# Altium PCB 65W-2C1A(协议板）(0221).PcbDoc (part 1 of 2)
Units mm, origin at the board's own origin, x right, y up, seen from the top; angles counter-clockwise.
Board outline 49.16 x 94.2 mm, 4 copper layers (Top Layer, Mid-Layer 1, Mid-Layer 2, Bottom Layer); 54 components, 359 nets, 243 pads, 110 vias.
Unrouted connection lines stored in the file: 1.
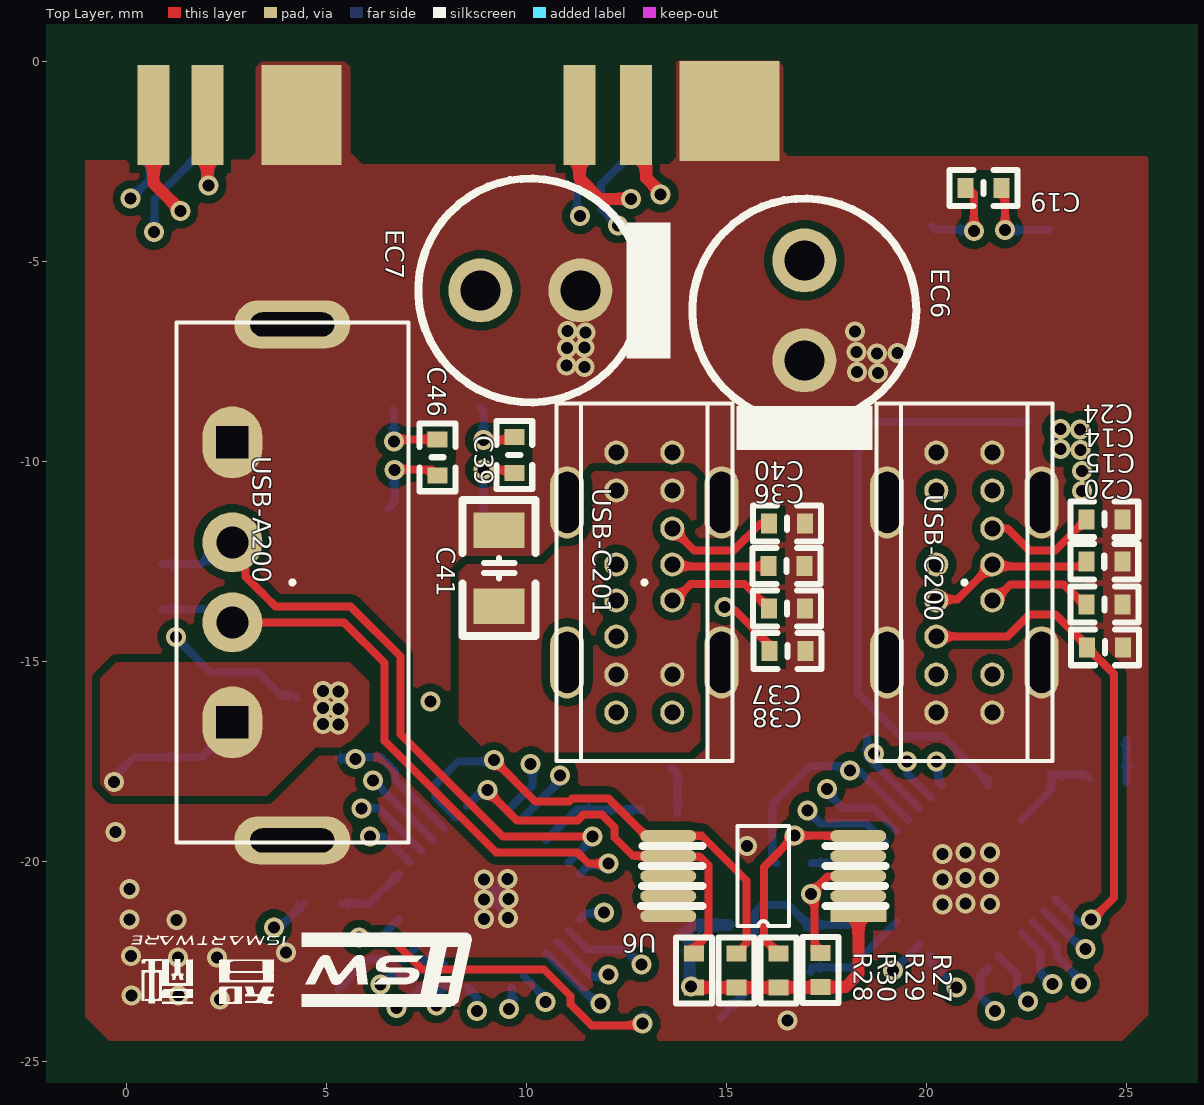
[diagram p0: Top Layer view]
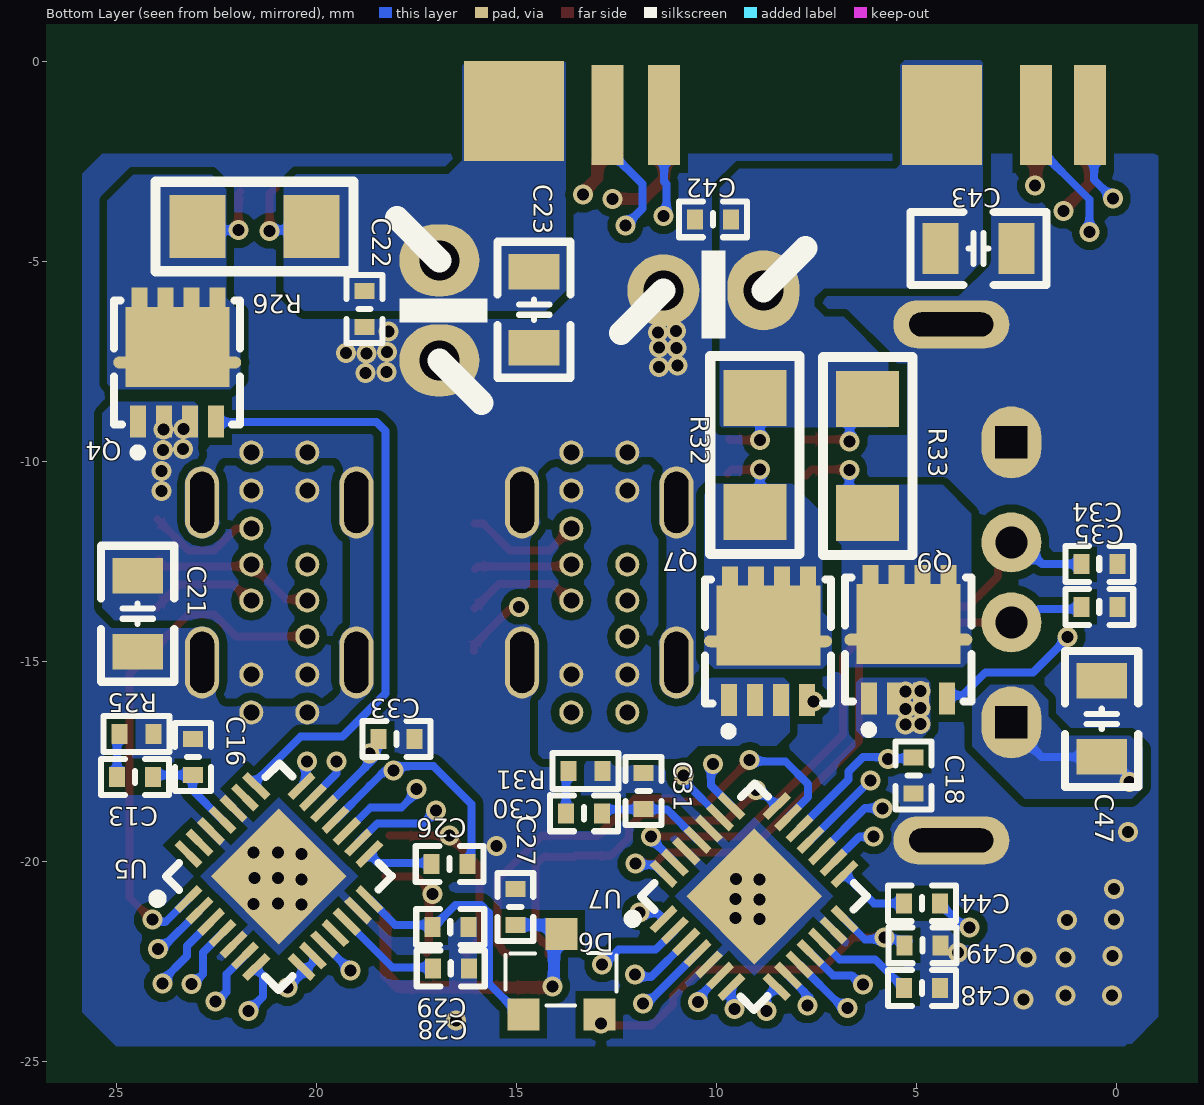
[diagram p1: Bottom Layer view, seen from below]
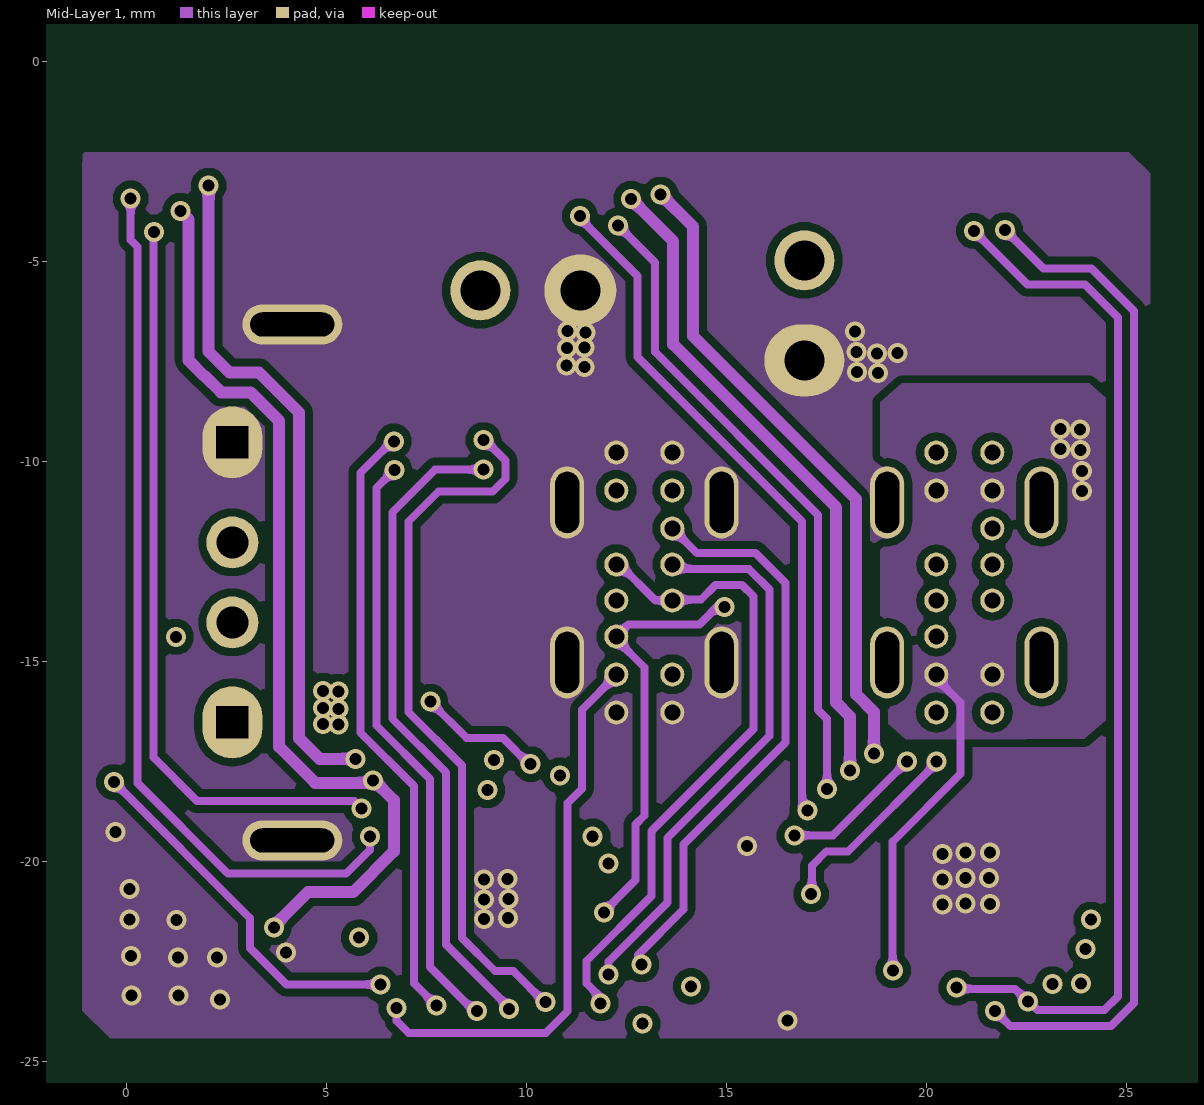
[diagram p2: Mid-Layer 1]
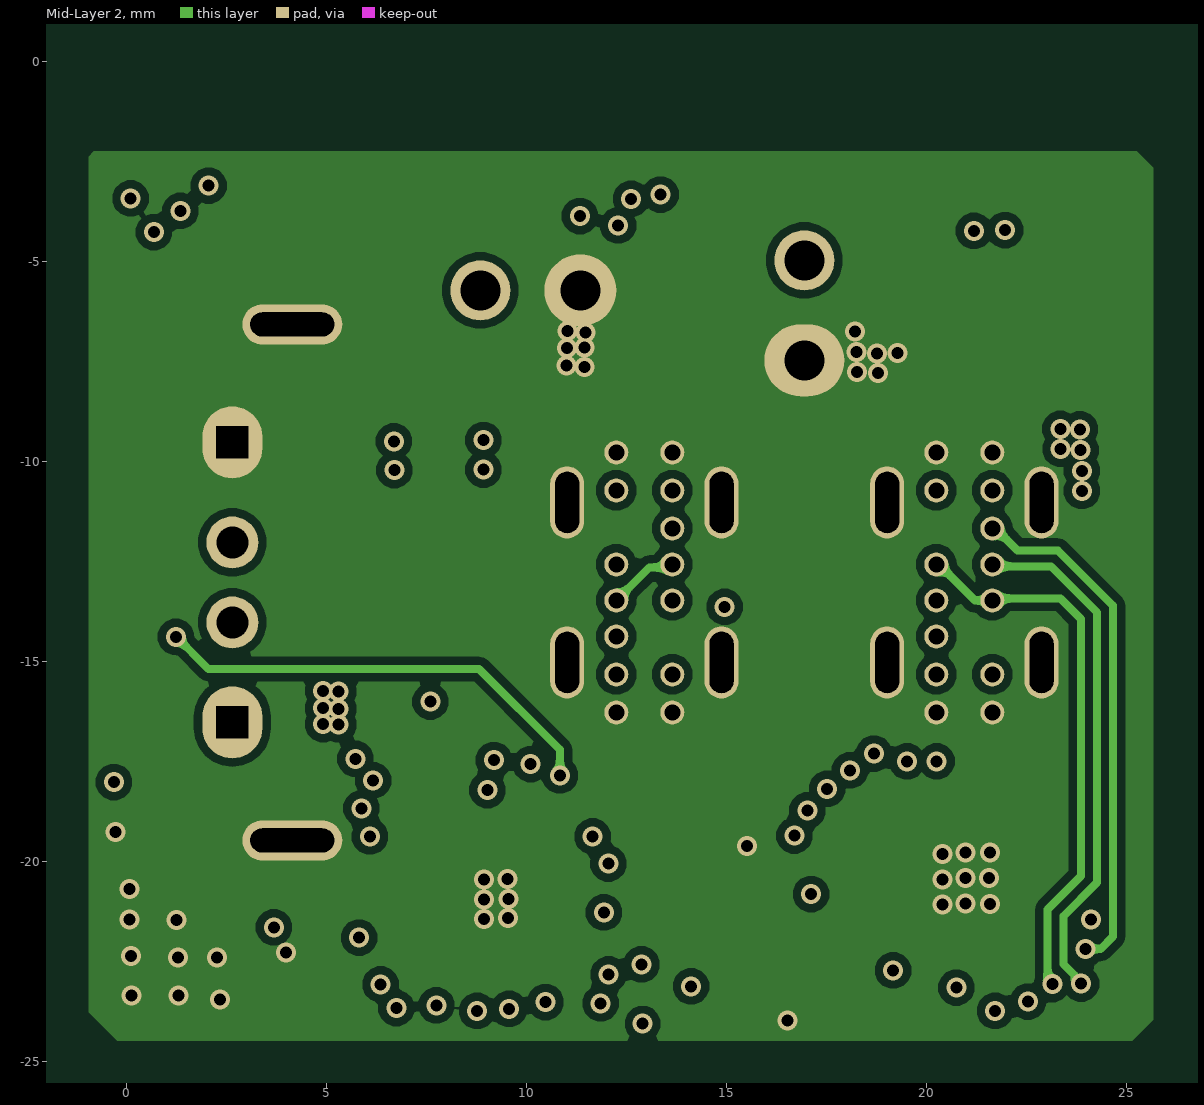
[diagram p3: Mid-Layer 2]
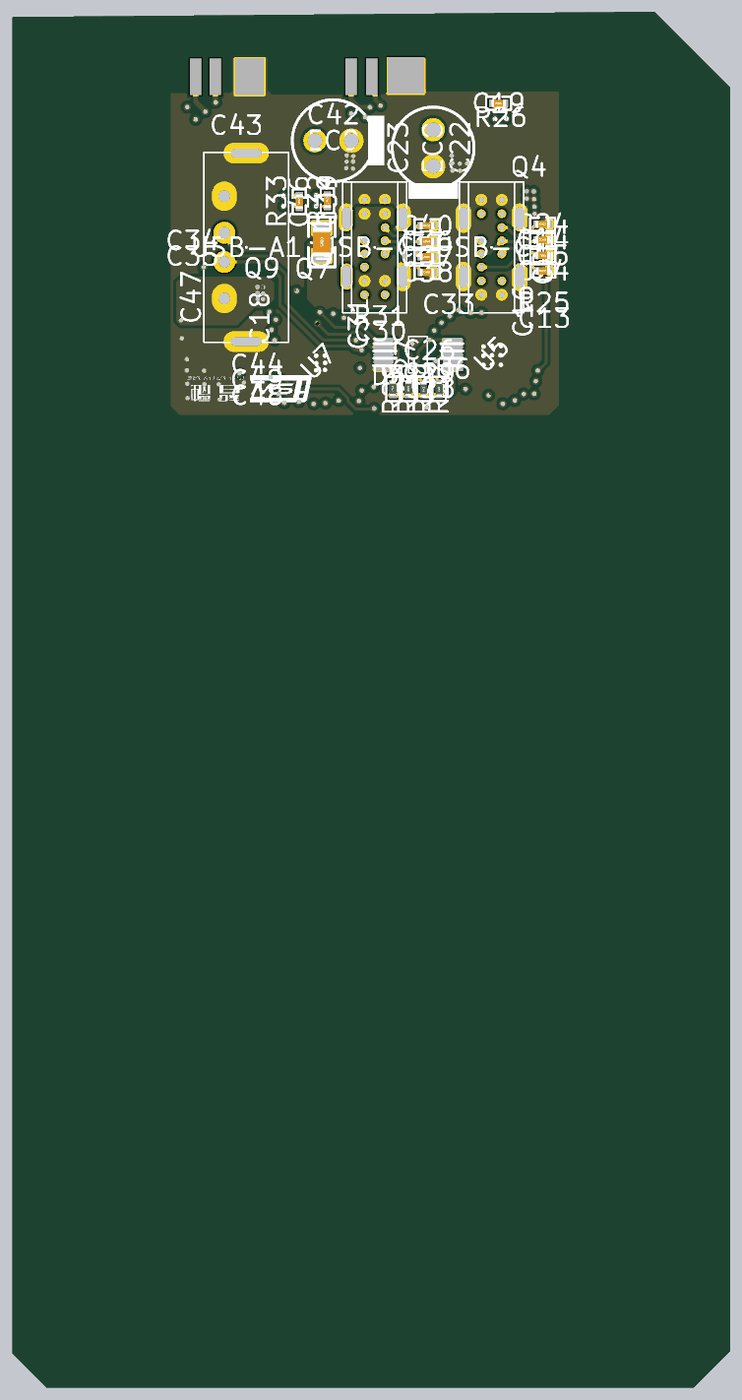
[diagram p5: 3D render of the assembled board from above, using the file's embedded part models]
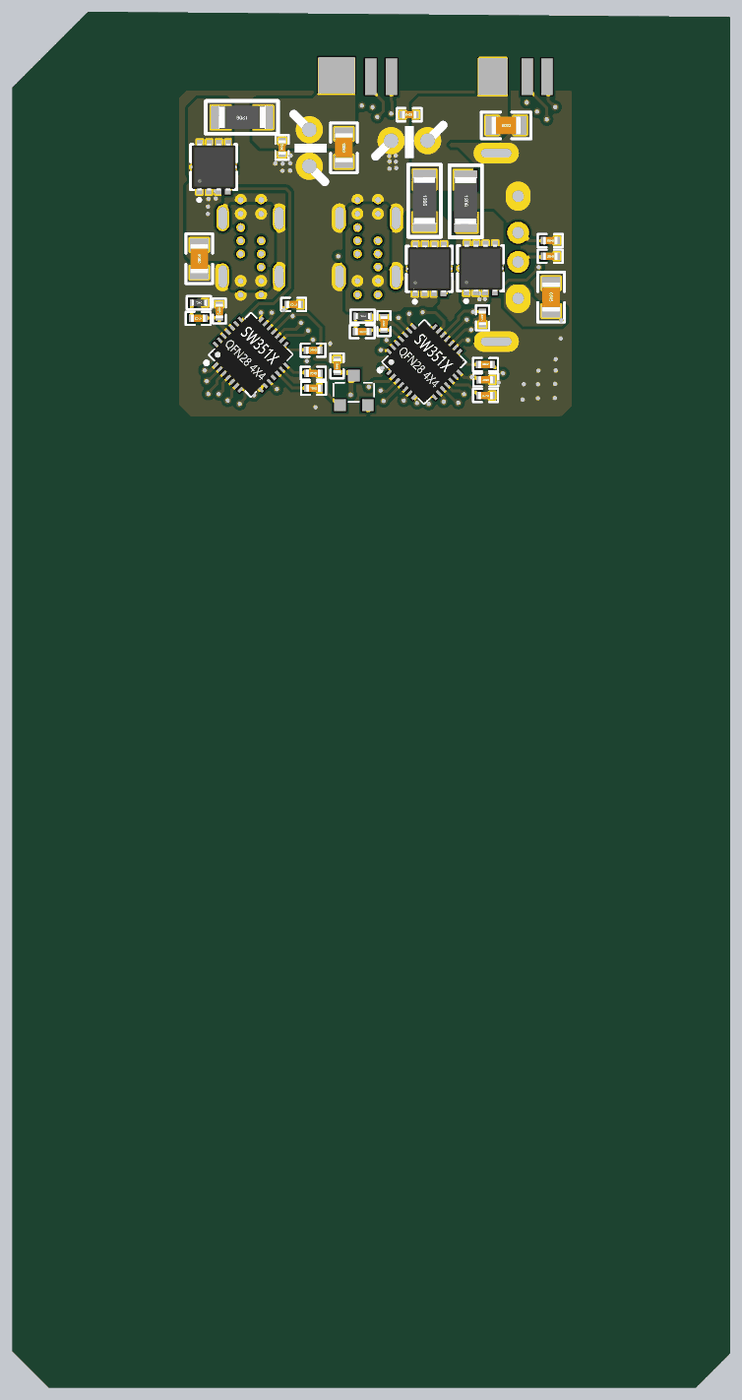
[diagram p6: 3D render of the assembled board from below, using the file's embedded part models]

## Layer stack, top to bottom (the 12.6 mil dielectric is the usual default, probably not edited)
Top Solder: solder mask 0.0102, Solder Resist, Dk 3.5
Top Layer: signal copper 0.0356
Dielectric1: core 0.32, FR-4, Dk 4.8
Mid-Layer 1: signal copper 0.0356
Dielectric2: prepreg 0.32, FR-4, Dk 4.8
Mid-Layer 2: signal copper 0.0356
Dielectric3: core 0.32, FR-4, Dk 4.8
Bottom Layer: signal copper 0.0356
Bottom Solder: solder mask 0.0102, Solder Resist, Dk 3.5

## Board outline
-11.88,2.75 -11.88,-88.76 -9.55,-91.09 34.78,-91.09 37.28,-88.59 37.28,-2.07 32.1,3.11

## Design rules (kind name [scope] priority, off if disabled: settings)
Clearance Clearance_2 [InNet('GND') And OnLayer('Mid-Layer 1') vs InNetClass('New Class')] p1: gap=0.8
Clearance Clearance_3 [InNet('GND') And OnLayer('Mid-Layer 2') vs InNetClass('New Class')] p2: gap=0.8
Clearance Clearance_1 [InNet('GND') And OnLayer('Top Layer') vs InNetClass('New Class')] p3: gap=1.2
Clearance [All] p4: gap=0.2
ComponentClearance [All] p1: gap=0 collisioncheckmode=3 verticalgap=0 showdistances=FALSE
HoleSize [All] p1 off: absolutevalues=TRUE maxlimit=2.54 minlimit=0.025 maxpercent=80.000 minpercent=20.000
MinimumSolderMaskSliver [All] p1 off: minsoldermaskwidth=0.254
NetAntennae [All] p1 off: netantennaetolerance=0
PlaneConnect [All] p1: planeconnectstyle=Direct reliefexpansion=0.508 reliefentries=4 reliefconductorwidth=0.254 reliefairgap=0.254
PolygonConnect [All] p1: connectstyle=Direct reliefconductorwidth=0.254 reliefentries=4 polygonreliefangle="90 Angle" airgapwidth=0.254
RoutingVias [All] p1: holewidth=0.3 width=0.5 viastyle="Through Hole" minholewidth=0.3 minwidth=0.5 maxholewidth=0.711 maxwidth=1.27
SilkToSilkClearance [All] p1 off: silktosilkclearance=0.254
SilkToSolderMaskClearance [IsPad] p1 off: minsilkscreentomaskgap=0.254 clearancetoexposedcopper=TRUE
SolderMaskExpansion [All] p1: expansion=0.102
Width [All] p1: maxlimit=3 minlimit=0.2 preferedwidth=0.2
23 further rules are at their usual default settings.

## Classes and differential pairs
net class "New Class": HHV HV NetC2_2 NetDB1_4
component class "P7-CEMK65W1A1CPD-P V0.2 20211227": CE1 CE2 RS2 RS3 RS4 RS5

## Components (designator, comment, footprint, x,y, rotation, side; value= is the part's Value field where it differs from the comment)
C13 "2.2nF/10V" "C 0402" 24.55,-17.88 r0 bottom
C14 "100pF/16V" "C 0402" 24.44,-12.5 r180 top
C15 "100pF/16V" "C 0402" 24.45,-13.57 r180 top
C16 "100pF/10V" "C 0402" 23.1,-17.38 r90 bottom
C18 "0.1uF/50V" "C 0402" 5.08,-17.85 r90 bottom
C19 "0.1uF/50V" "C 0402" 21.42,-3.16 r180 top
C20 "330pF/16V" "C 0402" 24.46,-14.64 r0 top (schematic designator C24)
C21 "10uF/25V" "C 0805" 24.48,-13.8 r90 bottom
C22 "0.1uF/50V" "C 0402" 18.81,-6.18 r90 bottom
C23 "22uF/25V" "C 0805" 14.57,-6.2 r90 bottom
C24 "330pF/16V" "C 0402" 24.44,-11.44 r0 top
C26 "0.1uF/50V" "C 0402" 16.68,-20.06 r180 bottom
C27 "Cap" "C 0402" 15.04,-21.13 r90 bottom
C28 "1uF/16V" "C 0402" 16.653,-22.667 r0 bottom
C29 "1uF/16V" "C 0402" 16.666,-21.636 r0 bottom
C30 "2.2nF/10V" "C 0402" 13.32,-18.79 r0 bottom
C31 "100pF/10V" "C 0402" 11.83,-18.23 r90 bottom
C33 "0.1uF/50V" "C 0402" 18.01,-16.93 r0 bottom
C34 "100pF/16V" "C 0402" 0.44,-12.56 r0 bottom
C35 "100pF/16V" "C 0402" 0.44,-13.63 r0 bottom
C36 "100pF/16V" "C 0402" 16.5,-12.61 r180 top
C37 "100pF/16V" "C 0402" 16.51,-13.67 r180 top
C38 "330pF/16V" "C 0402" 16.52,-14.73 r0 top
C39 "0.1uF/50V" "C 0402" 9.69,-9.83 r90 top
C40 "330pF/16V" "C 0402" 16.51,-11.55 r0 top
C41 "10uF/25V" "C 0805" 9.31,-12.66 r270 top
C42 "0.1uF/50V" "C 0402" 10.1,-3.94 r180 bottom
C43 "22uF/25V" "C 0805" 3.46,-4.67 r0 bottom
C44 "0.1uF/50V" "C 0402" 4.877,-21.04 r180 bottom
C46 "0.1uF/50V" "C 0402" 7.77,-9.89 r90 top
C47 "10uF/25V" "C 0805" 0.38,-16.43 r270 bottom
C48 "1uF/16V" "C 0402" 4.87,-23.16 r0 bottom
C49 "1uF/16V" "C 0402" 4.86,-22.09 r0 bottom
D6 "BAT54C/SOT-23" "SOD-23 - P" 13.89,-21.79 r180 bottom
EC6 "E - Cap" EC-5.5X9-P2.5-C#1 16.94,-6.218 r270 top locked (schematic designator EC8)
EC7 "E - Cap" EC-5.5X9-P2.5-C#2 10.09,-5.718 r0 top (schematic designator EC9)
Q4 "N MOS" PDFN-3*3 23.48,-7.52 r180 bottom
Q7 "N MOS" PDFN-3*3 8.71,-14.49 r180 bottom
Q9 "N MOS" PDFN-3*3 5.2,-14.45 r180 bottom
R25 "20K" "R 0402" 24.51,-16.81 r0 bottom
R26 "5mR" "R 1206" 21.56,-4.12 r0 bottom
R27 "2K" "R 0402" 17.35,-22.71 r90 top
R28 "2K" "R 0402" 14.18,-22.72 r270 top
R29 "2K" "R 0402" 16.29,-22.72 r90 top
R30 "2K" "R 0402" 15.24,-22.72 r270 top
R31 "20K" "R 0402" 13.29,-17.73 r0 bottom
R32 "5mR" "R 1206" 9.05,-9.83 r270 bottom
R33 "5mR" "R 1206" 6.23,-9.86 r270 bottom
U5 "SW3516P" SW351X_QFN28-4X4 20.95,-20.37 r225 bottom
U6 "MCU" MSOP10 18.29,-21.36 r180 top
U7 "SW3516P" SW351X_QFN28-4X4 9.07,-20.87 r225 bottom
USB-A200 "USB-A-5PIN" USB/AF/短体/10.0/直插/直边/蓝色/耐高温 4.14,-13.018 r0 top locked (schematic designator USB-A1)
USB-C200 "TYPE-C-14PIN" "TYPE-C 直立式外壳四脚14P" 20.94,-13.018 r0 top locked (schematic designator USB-C1)
USB-C201 "TYPE-C-14PIN" "TYPE-C 直立式外壳四脚14P" 12.94,-13.018 r0 top locked (schematic designator USB-C2)

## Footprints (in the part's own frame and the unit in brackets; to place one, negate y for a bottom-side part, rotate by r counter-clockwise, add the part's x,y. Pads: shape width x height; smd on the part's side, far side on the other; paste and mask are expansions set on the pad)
"C 0402" [mm] "无极性贴片电容"
  rect 0.4x0.5 smd: 1(-0.45,0) 2(0.45,0)
  silkscreen extent -0.85,-0.45 0.85,0.45, body extent -0.5,-0.26 0.5,0.26, height 0.53
"C 0805" [mm] "无极性贴片电容"
  rect 0.889x1.27 smd: 1(-0.95,0) 2(0.95,0)
  silkscreen extent -1.7,-0.91 1.7,0.91, body extent -1,-0.61 1,0.61, height 0.51
EC-5.5X9-P2.5-C#1 [mm]
  round 1.6 / inner round 1.5 / far side oval 1.8x2 hole 1 mask+0.03: 1(-1.25,0)
  round 1.6 / inner oval 1.8x2 / far side oval 1.8x2 hole 1 mask+0.03: 2(1.25,0)
  silkscreen extent -2.8,-2.8 3.49,2.8
EC-5.5X9-P2.5-C#2 [mm] "脚距2.5mm直径6.3mm高度7mm"
  round 1.6 / inner round 1.5 / far side oval 1.8x2 hole 1 mask+0.03: 1(-1.25,0)
  round 1.6 / inner round 1.8 / far side round 1.8 hole 1 mask+0.03: 2(1.25,0)
  silkscreen extent -2.8,-2.8 3.5,2.8
MSOP10 [mm]
  rect 1.4x0.3 smd mask+0.05: 1(0,0)
  oval 1.4x0.3 smd mask+0.05: 2(0,-0.5) 3(0,-1) 4(0,-1.5) 5(0,-2) 6(4.75,-2) 7(4.75,-1.5) 8(4.75,-1) 9(4.75,-0.5) 10(4.75,0)
  silkscreen extent -0.68,-2.25 5.43,0.25, body extent 0.7,-2.25 4.03,0.24, height 1.2
PDFN-3*3 [mm] "DFN3*3, PDFN3*3"
  rect 0.4x0.8 smd: 1(-0.992,-1.47) 2(-0.342,-1.47) 3(0.308,-1.47) 4(0.958,-1.47) 5(0.992,1.47) 6(0.341,1.47) 7(-0.309,1.47) 8(-0.959,1.47)
  oval 3.2x0.3 smd: 9(-0.012,0)
  rect 2.6x2 smd: 9(-0.005,0.393)
  silkscreen extent -1.59,-2.35 1.56,1.55, body extent -1.55,-1.6 1.55,1.6, height 0.8
"R 0402" [mm] "1/16W贴片电阻"
  rect 0.4x0.5 smd: 1(-0.425,0) 2(0.425,0)
  silkscreen extent -0.82,-0.45 0.83,0.45, body extent -0.52,-0.25 0.48,0.25, height 0.3
"R 1206" [mil] "1/4W贴片电阻"
  rect 55x62 smd: 1(-56.1,0) 2(56.1,0)
  silkscreen extent -97,-44 97,44, body extent -64,-31 62,31, height 22
"SOD-23 - P" [mm]
  rect 0.8x0.8 smd: 1(-0.95,-2.032) 2(0.95,-2.032) 3(0,-0.012)
  silkscreen extent -1.39,-1.81 1.38,-0.5
SW351X_QFN28-4X4 [mm] "28脚，长x宽x高：4x4x0.8mm，脚距：0.4mm"
  rect 0.2x0.8 smd: 1(-1.2,-2) 2(-0.8,-2) 3(-0.4,-2) 4(0,-2) 5(0.4,-2) 6(0.8,-2) 7(1.2,-2) 15(1.2,2) 16(0.8,2) 17(0.4,2) 18(0,2) 19(-0.4,2) 20(-0.8,2) 21(-1.2,2)
  rect 0.8x0.2 smd: 8(2,-1.2) 9(2,-0.8) 10(2,-0.4) 11(2,0) 12(2,0.4) 13(2,0.8) 14(2,1.2) 22(-2,1.2) 23(-2,0.8) 24(-2,0.4) 25(-2,0) 26(-2,-0.4) 27(-2,-0.8) 28(-2,-1.2)
  rect 2.4x2.4 smd: 29(0,0)
  silkscreen extent -2,-2.64 2,2.01, body extent -2.01,-2.01 2.01,2.01, height 0.75
"TYPE-C 直立式外壳四脚14P" [mm] "TYPE-C母座"
  round 0.6 hole 0.4: CC1(0.7,1.35) CC2(-0.7,-1.35) D+(-0.7,-0.45) D+(0.7,0.45) D-(-0.7,0.45) D-(0.7,-0.45) G(-0.7,-3.25) G(-0.7,3.25) G(0.7,-3.25) G(0.7,3.25) V(-0.7,-2.3) V(-0.7,2.3) V(0.7,-2.3) V(0.7,2.3)
  oval 0.85x1.8 hole 0.6 slot 1.53 at 90 deg: G(-1.93,-2) G(-1.93,2) G(1.93,-2) G(1.93,2)
  silkscreen extent -2.2,-4.47 2.2,4.47, body extent -2.2,-4.47 2.2,4.47, height 9.5
USB/AF/短体/10.0/直插/直边/蓝色/耐高温 [mm] "USB母座"
  oval 1.5x1.8 hole 0.8 square: 1(-1.5,3.5) 4(-1.5,-3.5)
  round 1.5 / inner round 1.3 / far side round 1.5 hole 0.8: 2(-1.5,1) 3(-1.5,-1)
  oval 2.9x1.2 / inner oval 2.5x1 / far side oval 2.9x1.2 hole 0.6 slot 2.1 at 0 deg: 5(0,-6.45) 6(0,6.45)
  silkscreen extent -2.9,-6.5 2.9,6.5, body extent -3.7,-6.5 3.7,6.5, height 6.7

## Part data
C13 C16 C18 C19 C20 C22 C23 C24 C26 C28 C29 C30 C31 C33 C38 C39 C40 C42 C43 C44 C46 C48 C49: library part CAP0603, "Capacitor"
C14 C15 C21 C34 C35 C36 C37 C41 C47: library part CAP0805, "Capacitor"
C27: "Capacitor"
D6: library part D3
EC6 EC7: "Electroytic Capacitor, 100uF/35V, ±20%, 105℃，Φ 6.5 * 12.0 mm"
Q4 Q7 Q9: library part AO3416_C479060
R25 R26 R27 R28 R29 R30 R31 R32 R33: library part RES, "Resistor"
U5 U7: library part SW3517, "IC"
U6: library part 153_MSOP10
USB-C200 USB-C201: "TYPE-C"

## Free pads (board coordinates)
  rect 0.8x2.5 smd far side: 0(0.67,-1.333) 0(2.02,-1.333) 0(11.32,-1.333) 0(12.738,-1.333)
  rect 0.8x2.5 smd: 0(0.67,-1.333) 0(2.02,-1.333) 0(11.32,-1.333) 0(12.738,-1.333)
  rect 2x2.5 smd far side: 0(4.37,-1.33)
  rect 2x2.5 smd: 0(4.37,-1.33)
  rect 2.5x2.5 smd far side: 0(15.07,-1.23)
  rect 2.5x2.5 smd: 0(15.07,-1.23)

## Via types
v1: diameter 0.5, hole 0.3, Top Layer to Bottom Layer, tented both sides, 110 vias

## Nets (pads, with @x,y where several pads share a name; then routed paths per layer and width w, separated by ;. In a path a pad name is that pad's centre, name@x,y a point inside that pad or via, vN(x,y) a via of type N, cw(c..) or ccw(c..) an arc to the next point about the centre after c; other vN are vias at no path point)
111: 
112: 
113: 
115: 
116: 
$$$3: 
$$$11: 
$$$13: 
$$$16: 
$$$18: 
$$$20: 
$$$24: 
$$$27: 
$$$28: 
$$$29: 
$$$31: 
$$$32: 
$$$37: 
$$$39: 
$$$40: 
$$$43: 
$$$51: 
AUX: 
BST2: 
BST_A: C26.1 U5.15 | length 1.7
  Bottom Layer w0.2: C26.1@17.12,-20.03 18.462,-20.03 U5.15@18.687,-19.804 ; U5.15@18.69,-19.83 U5.15@18.7,-19.82
BST_C: C44.1 U7.15 | length 1.7
  Bottom Layer w0.2: C44.1@5.37,-21.04 6.072,-21.04 U7.15@6.807,-20.304
CATHODE: 
CC1: 
CC1_A: C24.1 U5.2 USB-C200.CC1 | length 17.3
  Top Layer w0.2: USB-C200.CC1@21.56,-11.67 22.022,-11.67 22.57,-12.218 23.212,-12.218 C24.1@23.99,-11.44
  Mid-Layer 2 w0.2: USB-C200.CC1@21.65,-11.6 22.268,-12.218 23.278,-12.218 24.66,-13.6 24.66,-21.87 24.35,-22.18 v1(23.97,-22.18)
  Bottom Layer w0.2: U5.2@22.93,-21.219 23.881,-22.17 v1@23.94,-22.17
CC1_C: C40.1 U7.2 USB-C201.CC1 | length 19.5
  Top Layer w0.2: USB-C201.CC1@13.64,-11.668 14.19,-12.218 15.171,-12.218 15.839,-11.55 C40.1@16.06,-11.55
  Mid-Layer 1 w0.2: v1@12.85,-22.54 12.78,-22.47 12.78,-22.329 13.92,-21.189 13.92,-19.567 16.47,-17.017 16.47,-13.033 15.717,-12.28 14.252,-12.28 USB-C201.CC1@13.64,-11.668
  Bottom Layer w0.2: U7.2@11.05,-21.719 11.531,-22.2 12.46,-22.2 v1@12.84,-22.58
  other v1: 12.87,-22.57
CC2: 
CC2_A: C20.1 U5.1 USB-C200.CC2 | length 12.8
  Top Layer w0.2: USB-C200.CC2@20.24,-14.368 22.02,-14.368 22.57,-13.818 23.218,-13.818 C20.1@24.03,-14.63 ; C20.1@23.97,-14.66 C20.1@23.97,-14.62 ; C20.1@24.01,-14.64 24.68,-15.31 24.68,-20.9 v1@24.11,-21.47
  Bottom Layer w0.2: U5.1@23.213,-20.936 23.777,-21.5 v1@24.07,-21.5
  other v1: 24.11,-21.45
CC2_C: C38.1 U7.1 USB-C201.CC2 | length 12.8
  Top Layer w0.2: 15.2,-13.71 16.07,-14.58 C38.1@16.07,-14.73
  Mid-Layer 1 w0.2: v1@11.92,-21.26 12.72,-20.46 12.72,-19.07 12.94,-18.85 12.94,-15.14 12.242,-14.442 USB-C201.CC2@12.24,-14.368 ; USB-C201.CC2@12.21,-14.4 USB-C201.CC2@12.24,-14.368 ; v1(14.95,-13.63) v1@14.89,-13.63 ; v1@14.99,-13.53 v1@14.89,-13.63 ; USB-C201.CC2@12.24,-14.368 12.542,-14.068 14.32,-14.068 14.758,-13.63 v1@14.89,-13.63
  Bottom Layer w0.2: U7.1@11.333,-21.436 11.478,-21.29 v1@11.91,-21.29
  other v1: 11.93,-21.27
CC3: 
CC4: 
COMP: 
COMP2: 
COMP_A: C13.1 C16.1 U5.25 | length 2.5
  Bottom Layer w0.2: U5.25@22.364,-18.956 23.11,-18.21 C16.1@23.11,-17.83 ; C16.1@23.11,-17.78 C16.1@23.11,-17.83 ; C13.1@24.06,-17.92 23.97,-17.83 C16.1@23.11,-17.83
COMP_C: C30.1 C31.1 U7.25 | length 2.7
  Bottom Layer w0.2: U7.25@10.484,-19.456 11.25,-18.69 12.83,-18.69 C30.1@12.86,-18.72
CSN: 
CSNA: C46.1 Q9.5 Q9.6 Q9.7 Q9.8 Q9.9 R33.2 U7.8 | length 17.7
  Top Layer w0.2: v1@6.72,-10.18 6.73,-10.19 7.62,-10.19 C46.1@7.77,-10.34
  Mid-Layer 1 w0.2: v1(6.69,-10.21) 6.24,-10.66 6.24,-16.59 7.58,-17.93 7.58,-22.63 v1@8.71,-23.76
  Bottom Layer w0.2: R33.2@6.53,-11.17 6.69,-11.01 v1(6.69,-10.21) ; U7.8@8.504,-23.133 8.75,-23.378 v1@8.75,-23.8
  other v1: 8.76,-23.73
CSNC_A: C19.1 Q4.5 Q4.6 Q4.7 Q4.8 Q4.9 R26.2 U5.7 | length 28.6
  Top Layer w0.2: C19.1@21.91,-3.24 21.96,-3.29 v1(21.96,-4.21)
  Mid-Layer 1 w0.2: v1(21.71,-23.73) 22.09,-24.11 24.606,-24.11 25.18,-23.536 25.18,-6.23 24.12,-5.17 22.92,-5.17 v1(21.96,-4.21)
  Bottom Layer w0.2: U5.7@21.541,-22.659 21.35,-22.85 21.35,-23.37 v1(21.71,-23.73) ; v1(21.96,-4.21) 23.04,-4.21 R26.2@23.06,-4.19
CSNC_C: C39.1 Q7.5 Q7.6 Q7.7 Q7.8 Q7.9 R32.2 U7.7 | length 19.1
  Top Layer w0.2: v1(8.92,-10.2) 9.64,-10.2 C39.1@9.74,-10.3
  Mid-Layer 1 w0.2: v1(8.92,-10.2) 7.71,-10.2 6.64,-11.27 6.64,-16.424 7.98,-17.764 7.98,-22.07 v1@9.58,-23.67
  Bottom Layer w0.2: R32.2@8.87,-11.44 8.92,-11.39 v1(8.92,-10.2) ; v1@9.58,-23.74 9.636,-23.684 U7.7@9.636,-23.133
  other v1: 9.56,-23.68
CSPA: C39.2 C42.2 C43.2 C46.2 EC7.1 pad.0@4.37,-1.33 R32.1 R33.1 U7.6 U7.9 | length 38.6
  Top Layer w0.2: v1@6.68,-9.47 6.71,-9.44 C46.2@7.77,-9.44 ; v1(8.92,-9.46) 9.67,-9.46 C39.2@9.7,-9.43
  Mid-Layer 1 w0.2: v1(6.68,-9.49) 6.632,-9.49 5.84,-10.282 5.84,-16.77 7.18,-18.11 7.18,-23.04 v1@7.68,-23.54 ; v1@7.64,-23.58 v1@7.73,-23.67 ; v1@8.888,-9.39 v1@8.888,-9.382 ; v1@8.939,-9.441 9.47,-9.972 9.47,-10.428 9.148,-10.75 8.692,-10.75 7.79,-10.75 7.04,-11.5 7.04,-16.259 8.38,-17.599 8.38,-21.904 9.213,-22.737 9.667,-22.737 v1@10.46,-23.53
  Bottom Layer w0.2: R33.1@6.64,-8.71 6.68,-8.75 v1(6.68,-9.49) ; v1@7.69,-23.69 7.69,-23.381 U7.9@8.221,-22.85 ; R32.1@8.83,-8.64 8.92,-8.73 v1(8.92,-9.46) ; U7.6@9.919,-22.85 10.44,-23.371 v1@10.44,-23.55
  other v1: 7.74,-23.59 10.47,-23.51
CSPC: 
D+: 
DB+: 
DM: 
DMA: C35.2 U7.28 USB-A200.3 | length 16
  Top Layer w0.2: USB-A200.3@2.203,-14.267 USB-A200.3@2.546,-13.924 ; USB-A200.3@2.64,-14.018 5.433,-14.018 6.45,-15.036 6.45,-16.984 9.237,-19.77 11.272,-19.77 11.552,-20.05 v1(12.04,-20.05)
  Bottom Layer w0.2: C35.2@0.9,-13.68 1.95,-13.68 2.289,-14.018 USB-A200.3@2.64,-14.018 ; U7.28@11.333,-20.304 11.557,-20.08 v1@11.87,-20.08
DMA2: 
DMA2-R: 
DMC: 
DMC_A: C15.2 U5.4 USB-C200.D- | length 18.1
  Top Layer w0.2: USB-C200.D-@21.64,-13.468 21.692,-13.468 22.09,-13.07 23.43,-13.07 C15.2@24,-13.64
  Mid-Layer 2 w0.2: USB-C200.D-@20.26,-12.52 21.208,-13.468 USB-C200.D-@21.64,-13.468 ; USB-C200.D-@21.65,-13.36 21.71,-13.42 23.349,-13.42 23.86,-13.931 23.86,-20.357 23.02,-21.197 23.02,-22.96 v1@23.13,-23.07
  Bottom Layer w0.2: U5.4@22.364,-21.784 22.85,-22.27 22.85,-22.81 23.1,-23.06 v1(23.14,-23.06)
DMC_C: C37.2 U7.4 USB-C201.D- | length 20.8
  Top Layer w0.2: USB-C201.D-@13.68,-13.48 14.1,-13.06 15.45,-13.06 C37.2@16.06,-13.67
  Mid-Layer 1 w0.2: v1(11.85,-23.54) 11.85,-23.398 11.5,-23.048 11.5,-22.478 13.12,-20.858 13.12,-19.236 15.67,-16.686 15.67,-13.364 15.386,-13.08 14.722,-13.08 14.352,-13.45 USB-C201.D-@13.68,-13.45 ; USB-C201.D-@12.29,-12.54 13.218,-13.468 USB-C201.D-@13.64,-13.468
  Bottom Layer w0.2: U7.4@10.484,-22.284 11.76,-23.56 v1@11.87,-23.56 ; v1@11.85,-23.57 v1@11.88,-23.57
DP: 
DPA: C34.2 U7.27 USB-A200.2 | length 16.2
  Top Layer w0.2: USB-A200.2@2.64,-12.018 2.64,-12.37 2.972,-12.701 2.972,-12.872 3.307,-13.207 cw(c2.64,-14.018) 3.452,-13.352 3.718,-13.618 5.598,-13.618 6.85,-14.87 6.85,-16.818 9.402,-19.37 v1(11.65,-19.37)
  Bottom Layer w0.2: C34.2@0.89,-12.56 1.873,-12.56 2.363,-12.07 USB-A200.2@2.63,-12.07 ; U7.27@11.05,-20.021 v1@11.6,-19.471
DPA2-R: 
DPC: 
DPC_A: C14.2 U5.3 USB-C200.D+ | length 19.2
  Top Layer w0.2: USB-C200.D+@20.17,-13.44 20.769,-13.44 USB-C200.D+@21.64,-12.568 21.69,-12.618 23.792,-12.618 C14.2@23.96,-12.45
  Mid-Layer 2 w0.2: USB-C200.D+@21.64,-12.568 21.69,-12.618 23.113,-12.618 24.26,-13.766 24.26,-20.522 23.42,-21.362 23.42,-22.562 23.69,-22.832 23.69,-22.95 v1@23.82,-23.08
  Bottom Layer w0.2: U5.3@22.647,-21.501 23.25,-22.104 23.25,-22.36 v1@23.89,-23
  other v1: 23.86,-23.05
DPC_C: C36.2 U7.3 USB-C201.D+ | length 19.9
  Top Layer w0.2: USB-C201.D+@13.64,-12.568 13.69,-12.618 15.988,-12.618 C36.2@16.05,-12.68
  Mid-Layer 1 w0.2: v1@12.01,-22.87 v1@12.01,-22.82 ; v1(12.05,-22.82) 12.05,-22.493 13.52,-21.024 13.52,-19.401 16.07,-16.851 16.07,-13.199 15.551,-12.68 13.752,-12.68 USB-C201.D+@13.64,-12.568
  Mid-Layer 2 w0.2: USB-C201.D+@12.24,-13.468 13.064,-12.645 13.535,-12.645 USB-C201.D+@13.62,-12.56
  Bottom Layer w0.2: U7.3@10.767,-22.001 11.646,-22.88 v1@12.03,-22.88
EN: 
FB-G: 
FB_C: 
FB_IC: 
GATEA: Q9.4 U7.23 | length 16.6
  Mid-Layer 2 w0.2: v1@1.2,-14.34 2.04,-15.18 8.81,-15.18 10.83,-17.2 v1(10.83,-17.845)
  Bottom Layer w0.2: v1@1.21,-14.38 2.1,-15.27 3.29,-15.27 3.859,-15.839 4.161,-15.839 Q9.4@4.242,-15.92 ; U7.23@9.919,-18.89 10.773,-18.036 10.773,-17.877 v1@10.85,-17.8
  other v1: 1.23,-14.38
GATEC_A: Q4.4 U5.22 | length 15.1
  Bottom Layer w0.2: 18.66,-16.17 18.285,-15.795 18.285,-9.235 18.51,-9.01 Q4.4@22.48,-9.01 ; 18.661,-16.169 18.71,-16.218 18.71,-16.22 19.358,-16.868 20.406,-16.868 21.526,-17.989 U5.22@21.526,-18.096 ; Q4.4@22.5,-9.012 Q4.4@22.522,-8.99
GATEC_C: Q7.4 U7.22 | length 4.6
  Top Layer w0.2: v1@10.058,-17.56 v1(10.1,-17.56)
  Mid-Layer 1 w0.2: v1(7.59,-16) 8.5,-16.91 9.408,-16.91 10.098,-17.6 v1@10.19,-17.6
  Bottom Layer w0.2: U7.22@9.636,-18.607 10.15,-18.093 v1@10.15,-17.48
GND: 
GND2: 
GND_FIELD_SIGNAL: 
GNDA: 
GNDC1: 
GNDC2: 
HD: 
HGATE2: 
HGATE_A: pad.0@12.738,-1.333 U5.17 | length 21.7
  Mid-Layer 1 w0.2: v1(12.286,-4.095) 13.21,-5.019 13.21,-7.254 17.285,-11.329 17.285,-16.208 17.51,-16.432 v1(17.51,-18.18)
  Bottom Layer w0.2: v1(12.286,-4.095) 11.862,-3.671 11.862,-3.06 12.738,-2.183 pad.0@12.738,-1.333 ; v1@17.48,-18.24 17.88,-18.64 18.654,-18.64 U5.17@19.253,-19.239
HGATE_C: pad.0@2.02,-1.333 U7.17 | length 24.5
  Mid-Layer 1 w0.2: v1(0.68,-4.26) 0.67,-4.27 0.67,-17.39 1.76,-18.48 5.69,-18.48 5.865,-18.655 v1(5.865,-18.665)
  Bottom Layer w0.2: v1@0.69,-4.15 0.69,-3.44 2.02,-2.11 pad.0@2.02,-1.333 ; pad.0@1.72,-1.41 pad.0@1.92,-1.21 ; v1(5.865,-18.665) 5.87,-18.66 6.294,-18.66 U7.17@7.373,-19.739
HHV: 
HV: 
HVDC: 
INCAT: 
IS: 
L: 
LG: 
LGATE2: 
LGATE_A: pad.0@11.32,-1.333 U5.16 | length 22
  Mid-Layer 1 w0.2: v1(11.331,-3.859) 11.331,-3.917 12.77,-5.357 12.77,-7.379 16.885,-11.495 16.885,-18.585 v1(17.02,-18.72)
  Bottom Layer w0.2: pad.0@11.32,-1.333 11.32,-2.994 11.254,-3.06 11.254,-3.701 11.35,-3.797 v1@11.35,-3.81 ; v1@17.06,-18.77 17.33,-19.04 18.489,-19.04 U5.16@18.97,-19.521
LGATE_C: pad.0@0.67,-1.333 U7.16 | length 25.5
  Mid-Layer 1 w0.2: v1@0.1,-3.4 0.1,-4.458 0.27,-4.628 0.27,-18.034 2.536,-20.3 5.484,-20.3 6.08,-19.704 v1(6.08,-19.37)
  Bottom Layer w0.2: v1(0.1,-3.42) 0.57,-2.95 0.57,-1.433 pad.0@0.67,-1.333 ; v1@6.18,-19.38 6.449,-19.38 U7.16@7.09,-20.021
LSG: 
LSGA: 
LSGC: 
MOD: 
N: 
N16857873: 
N16857912: 
N16858127: 
N16870552: 
N16870687: 
N16870705: 
N16870765: 
N16874562: 
N16975475: 
NetBD1_1: 
NetC1_2: 
NetC2_1: 
NetC2_2: 
NetC3_2: 
NetC4_1: 
NetC4_2: 
NetC5_1: 
NetC5_2: 
NetC6_1: 
NetC6_2: 
NetC7_1: 
NetC7_2: 
NetC8_1: 
NetC10_1: 
NetC11_1: 
NetC11_2: 
NetC12_1: 
NetC13_2: C13.2 R25.2 | length 1.1
  Bottom Layer w0.2: C13.2@25,-18.02 R25.2@25,-16.95
NetC14_1: 
NetC14_2: 
NetC15_1: 
NetC15_2: 
NetC16_1: 
NetC17_1: 
NetC19_1: 
NetC20_1: 
NetC21_1: 
NetC22_1: 
NetC22_2: 
NetC23_1: 
NetC23_2: 
NetC24_2: 
NetC25_1: 
NetC25_2: 
NetC27_2: 
NetC28_1: 
NetC28_2: 
NetC29_1: 
NetC29_2: 
NetC30_1: 
NetC30_2: C30.2 R31.2 | length 1.2
  Bottom Layer w0.2: R31.2@13.62,-17.66 13.77,-17.81 C30.2@13.77,-18.79
NetC32_1: 
NetC33_1: 
NetC35_1: 
NetC35_2: 
NetC37_1: 
NetC200_2: 
NetC201_2: 
NetC202_2: 
NetC203_2: 
NetC204_2: 
NetC205_2: 
NetC206_1: 
NetC207_1: 
NetC208_1: 
NetC208_2: 
NetC209_1: 
NetC209_2: 
NetC210_2: 
NetC211_2: 
NetC219_1: 
NetC220_1: 
NetC221_2: 
NetC222_1: 
NetC224_2: 
NetC226_2: 
NetC227_1: 
NetC228_1: 
NetCE2_1: 
NetCX1_1: 
NetCX1_2: 
NetCY2_1: 
NetD1_2: 
NetD2_1: 
NetD2_2: 
NetD3_1: 
NetD3_2: 
NetD4_1: 
NetD4_2: 
NetD5_1: 
NetD5_2: 
NetD6_1: 
NetD6_2: 
NetD200_1: 
NetD201_1: 
NetD202_1: 
NetD203_1: 
NetD205_1: 
NetD205_2: 
NetD206_1: 
NetD207_1: 
NetD208_1: 
NetD209_1: 
NetD209_2: 
NetD210_1: 
NetD211_1: 
NetD211_2: 
NetD212_1: 
NetD213_1: 
NetD214_1: 
NetD215_1: 
NetD215_2: 
NetDB1_1: 
NetDB1_2: 
NetDB1_4: 
NetEC8_1: 
NetF1_1: 
NetJ2_2: 
NetJ2_3: 
NetL3_1: 
NetL4_1: 
NetNTC1_1: 
NetNTC2_1: 
NetNTC200_1: 
NetQ1_G: 
NetQ2_8: 
NetQ2_G: 
NetQ3_4: 
NetQ3_G: 
NetQ4_2: 
NetQ4_G: 
NetQ5_G: 
NetQ6_G: 
NetQ7_1: 
NetQ7_2: 
NetQ8_1: 
NetQ8_2: 
NetQ204_1: 
NetQ204_2: 
NetQ205_1: 
NetQ206_1: 
NetQ207_1: 
NetR1_1: 
NetR8_2: 
NetR9_1: 
NetR9_2: 
NetR11_1: 
NetR13_1: 
NetR14_1: 
NetR20_2: 
NetR21_1: 
NetR22_1: 
NetR23_1: 
NetR29_1: 
NetR30_2: 
NetR31_2: 
NetR34_1: 
NetR36_2: 
NetR37_1: 
NetR40_2: 
NetR41_2: 
NetR51_1: 
NetR200_2: 
NetR201_2: 
NetR202_2: 
NetR203_1: 
NetR204_1: 
NetR205_1: 
NetR206_1: 
NetR211_2: 
NetR212_1: 
NetR224_2: 
NetR225_2: 
NetR226_2: 
NetR227_2: 
NetR229_2: 
NetR230_2: 
NetR232_1: 
NetR236_2: 
NetR237_2: 
NetR238_2: 
NetR239_2: 
NetR240_2: 
NetR241_2: 
NetR243_2: 
NetR244_2: 
NetR246_2: 
NetR247_2: 
NetR249_2: 
NetU201_3: 
NetU202_12: 
NetU202_13: 
NewNet01: 
NewNet2: 
NewNet03: 
NewNet003: 
NewNet4: 
NewNet04: 
NewNet05: 
NewNet5: 
NewNet6: 
NewNet7: 
NewNet8: 
NewNet9: 
NewNet10: 
NewNet11: 
NewNet12: 
NewNet13: 
NewNet14: 
NewNet15: 
NewNet16: 
NewNet17: 
NewNet18: 
NewNet19: 
NewNet20: 
NewNet21: 
NewNet22: 
NewNet23: 
NewNet24: 
NewNet26: 
NewNet28: 
NewNet29: 
NULL1: 
OPTO1: 
OPTO2: 
P1.5: 
PFC: 
PLUG: 
PLUGA: 
POWER_IN: 
SCK: 
SCL: 
SCL_A: R27.2 U5.21 U6.3 | length 8.6
  Top Layer w0.2: v1@17.2,-20.81 17.2,-22.22 R27.2@17.26,-22.28 ; v1@17.2,-20.69 17.52,-20.37 18.28,-20.37 U6.3@18.29,-20.36
  Mid-Layer 1 w0.2: v1@17.13,-20.84 17.13,-20.1 17.49,-19.74 18.038,-19.74 20.27,-17.508 v1@20.27,-17.38
  Bottom Layer w0.2: v1@20.29,-17.38 20.29,-18.013 U5.21@20.384,-18.107
  other v1: 17.11,-20.81 20.25,-17.49
SCL_C: R28.1 U6.7 U7.21 | length 9.6
  Top Layer w0.2: v1@9,-18.22 v1@9.005,-18.215 ; v1@9.06,-18.27 9.76,-18.97 11.272,-18.97 11.422,-18.82 11.878,-18.82 12.2,-19.142 12.2,-19.4 12.65,-19.85 13.53,-19.85 13.56,-19.88 14.34,-19.88 14.54,-20.08 14.54,-21.81 14.21,-22.14 R28.1@14.21,-22.32
  Bottom Layer w0.2: U7.21@8.504,-18.607 v1@9.03,-18.082
  other v1: 9.02,-18.21
SDA: 
SDA_A: R29.2 U5.20 U6.5 | length 9.7
  Top Layer w0.2: R29.2@16.29,-22.295 16.24,-22.295 16.14,-22.195 16.14,-22.145 15.93,-21.935 15.93,-20.13 16.71,-19.35 U6.5@18.18,-19.35
  Mid-Layer 1 w0.2: v1@16.66,-19.33 16.67,-19.34 17.66,-19.34 v1(19.51,-17.49)
  Bottom Layer w0.2: v1@19.51,-17.5 19.51,-17.799 U5.20@20.101,-18.39
  other v1: 16.69,-19.35
SDA_C: R30.1 U6.6 U7.20 | length 12.3
  Top Layer w0.2: v1@9.16,-17.45 v1@9.175,-17.465 ; v1(9.18,-17.46) 10.22,-18.5 11.058,-18.5 11.138,-18.42 12.044,-18.42 12.983,-19.36 U6.6@13.54,-19.36 13.55,-19.35 14.376,-19.35 15.49,-20.464 15.49,-22.045 15.39,-22.145 15.39,-22.195 15.29,-22.295 R30.1@15.24,-22.295
  Bottom Layer w0.2: U7.20@8.221,-18.89 7.72,-18.389 7.72,-18.06 8.29,-17.49 v1@9.15,-17.49
SGND: C14.1 C15.1 C16.2 C18.1 C20.2 C21.1 C22.1 C23.1 C24.2 C27.2 C28.1 C29.1 C31.2 C33.1 C34.1 C35.1 C36.1 C37.1 C38.2 C40.2 C41.1 C42.1 C43.1 C47.1 C48.1 C49.1 EC6.2 EC7.2 pad.0@4.37,-1.33 pad.0@15.07,-1.23 R25.1 R31.1 U5.5 U5.13 U5.24 U5.26 U5.29 U6.10 U7.5 U7.13 U7.24 U7.26 U7.29 USB-A200.1 USB-A200.5 USB-A200.6 USB-C200.G USB-C201.G | length 3.1
  Top Layer w0.2: v1@18.755,-7.805 v1(18.78,-7.78)
  Bottom Layer w0.2: v1(8.93,-21.43) 8.93,-21.19 8.97,-21.15 U7.29@8.97,-20.95 ; v1(8.93,-20.95) U7.29@8.97,-20.95 ; v1(8.93,-20.44) 8.93,-20.73 U7.29@9.07,-20.87 ; v1(9.52,-20.43) 9.51,-20.43 U7.29@9.07,-20.87 ; v1(9.53,-21.41) 9.53,-21.33 U7.29@9.07,-20.87 ; v1(9.54,-20.93) 9.48,-20.87 U7.29@9.07,-20.87 ; U7.29@8.97,-20.95 9.04,-20.88 9.06,-20.88 U7.29@9.07,-20.87
  other v1: 16.52,-23.97 2.33,-23.44 0.12,-23.34 1.29,-23.35 1.28,-22.39 2.26,-22.39 0.107,-22.363 3.978,-22.274 1.25,-21.46 0.07,-21.44 20.39,-21.07 21.58,-21.06 20.97,-21.04 0.07,-20.68 20.39,-20.44 20.97,-20.41 21.56,-20.41 20.39,-19.81 20.97,-19.77 21.58,-19.77 15.51,-19.61 -0.28,-19.26 18.258,-7.76 11.45,-7.63 10.99,-7.59 18.76,-7.29 18.25,-7.26 19.27,-7.28 11.01,-7.16 11.45,-7.14 11.47,-6.77 11.02,-6.73 18.21,-6.74
SW2: 
SW_A: C26.2 pad.0@11.32,-1.333 U5.18 | length 25.6
  Top Layer w0.3: pad.0@11.32,-1.333 11.32,-2.92 11.828,-3.428 12.558,-3.428 v1@12.58,-3.45
  Mid-Layer 1 w0.3: v1(12.61,-3.428) 12.61,-3.439 13.66,-4.49 13.66,-7.067 17.735,-11.142 17.735,-16.021 18.08,-16.366 v1(18.08,-17.72)
  Bottom Layer w0.2: C26.2@16.24,-20.05 16.14,-19.95 16.14,-18.56 17.09,-17.61 17.97,-17.61 v1(18.08,-17.72) 18.3,-17.72 18.38,-17.8 ; 18.33,-17.8 18.38,-17.8 ; U5.18@19.536,-18.956 18.68,-18.1 18.38,-17.8
SW_C: C44.2 pad.0@0.67,-1.333 U7.18 | length 29.1
  Top Layer w0.3: pad.0@0.67,-1.333 0.67,-3.04 v1@1.35,-3.72 ; v1(1.34,-3.73) v1@1.37,-3.76
  Mid-Layer 1 w0.3: v1(1.34,-3.73) 1.55,-3.94 1.55,-7.47 1.94,-7.86 ; 1.946,-7.854 2.361,-8.268 3.096,-8.268 3.81,-8.983 3.81,-17.127 4.713,-18.03 6.1,-18.03 v1(6.16,-17.97) 6.19,-17.97 6.68,-18.46 6.68,-19.74 5.66,-20.76 4.53,-20.76 v1@3.7,-21.59
  Bottom Layer w0.2: v1@3.69,-21.67 3.797,-21.67 C44.2@4.427,-21.04 ; v1@6.23,-18.03 U7.18@7.656,-19.456
  other v1: 3.68,-21.64
TTCK: 
TTD: 
V+: 
VBUS: 
VBUSA: C47.2 Q9.1 Q9.2 Q9.3 U7.11 USB-A200.4 | length 14.5
  Mid-Layer 1 w0.2: v1(-0.32,-18.01) 3.082,-21.412 3.082,-22.156 3.996,-23.07 v1(6.35,-23.07)
  Bottom Layer w0.2: v1(-0.32,-18.01) -0.32,-17.929 -0.243,-17.852 -0.243,-17.812 0.19,-17.38 1.88,-17.38 USB-A200.4@2.71,-16.55 ; v1@6.36,-23.11 6.63,-22.84 7.1,-22.84 U7.11@7.656,-22.284
  other v1: 4.91,-16.56 5.29,-16.57 5.29,-16.18 4.91,-16.16 5.29,-15.75 4.91,-15.73
VBUSC1: 
VBUSC2: 
VBUSC_A: C21.2 Q4.1 Q4.2 Q4.3 U5.10 USB-C200.V | length 9.1
  Mid-Layer 1 w0.2: v1@19.15,-22.63 19.15,-19.5 20.84,-17.81 20.84,-16.02 20.24,-15.42 USB-C200.V@20.24,-15.318
  Bottom Layer w0.2: v1@19.23,-22.656 U5.10@19.819,-22.067
  other v1: 19.16,-22.72 23.88,-10.73 23.88,-10.23 23.85,-9.71 23.35,-9.68 23.83,-9.19 23.34,-9.18
VBUSC_C: C41.2 Q7.1 Q7.2 Q7.3 U7.10 USB-C201.V | length 15.2
  Mid-Layer 1 w0.2: v1@6.75,-23.8 6.75,-23.98 7.05,-24.28 10.478,-24.28 11.02,-23.738 11.02,-18.538 11.38,-18.178 11.38,-16.2 USB-C201.V@12.26,-15.32
  Bottom Layer w0.2: v1@6.866,-23.64 U7.10@7.939,-22.567
  other v1: 6.74,-23.66
VCC: 
VDD1: 
VDD2: 
VDD_A: C28.2 U5.12 | length 2.6
  Bottom Layer w0.2: C28.2@17.1,-22.76 C28.2@17.103,-22.76 ; C28.2@17.13,-22.64 18.114,-22.64 U5.12@19.253,-21.501
VDD_C: C48.2 U7.12 | length 2.6
  Bottom Layer w0.2: C48.2@5.28,-23.19 5.3,-23.19 6.05,-22.44 6.934,-22.44 U7.12@7.373,-22.001
VDRV_A: C29.2 D6.1 U5.14 | length 6.6
  Bottom Layer w0.2: D6.1@14.84,-23.92 14.84,-23.912 15.704,-23.048 15.704,-21.274 15.891,-21.086 16.54,-21.086 C29.2@17.06,-21.606 ; C29.2@17.06,-21.66 C29.2@17.06,-21.606 ; C29.2@17.116,-21.636 17.09,-21.636 C29.2@17.06,-21.606 ; C29.2@17.14,-21.58 18.043,-21.58 U5.14@18.687,-20.936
